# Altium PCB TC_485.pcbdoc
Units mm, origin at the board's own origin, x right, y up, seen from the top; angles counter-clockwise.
Board outline 61.6 x 60 mm, 2 copper layers (Top Layer, Bottom Layer); 41 components, 25 nets, 95 pads, 58 vias.
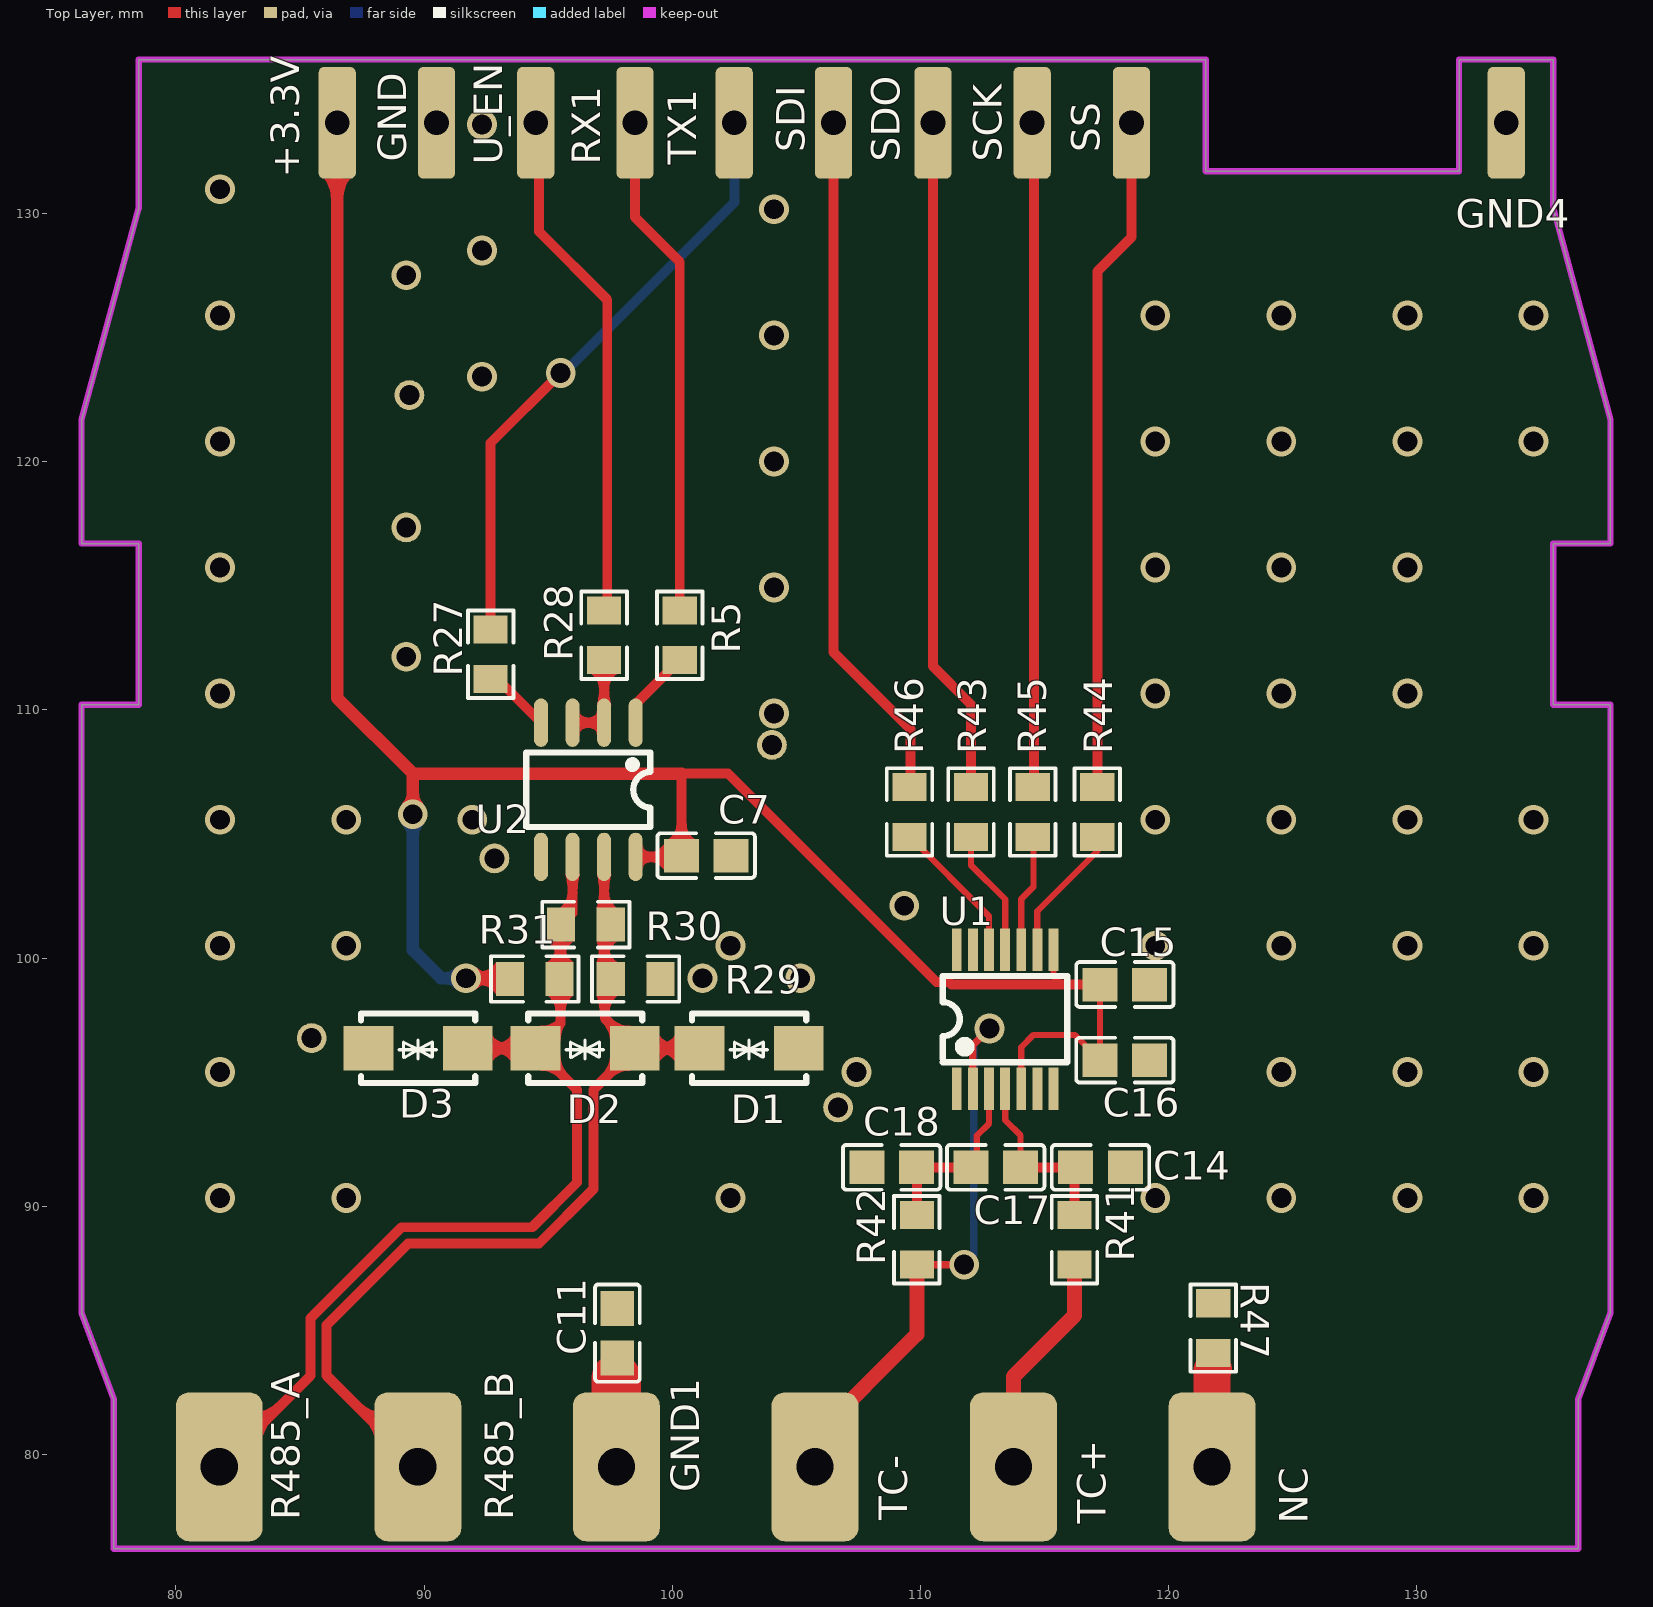
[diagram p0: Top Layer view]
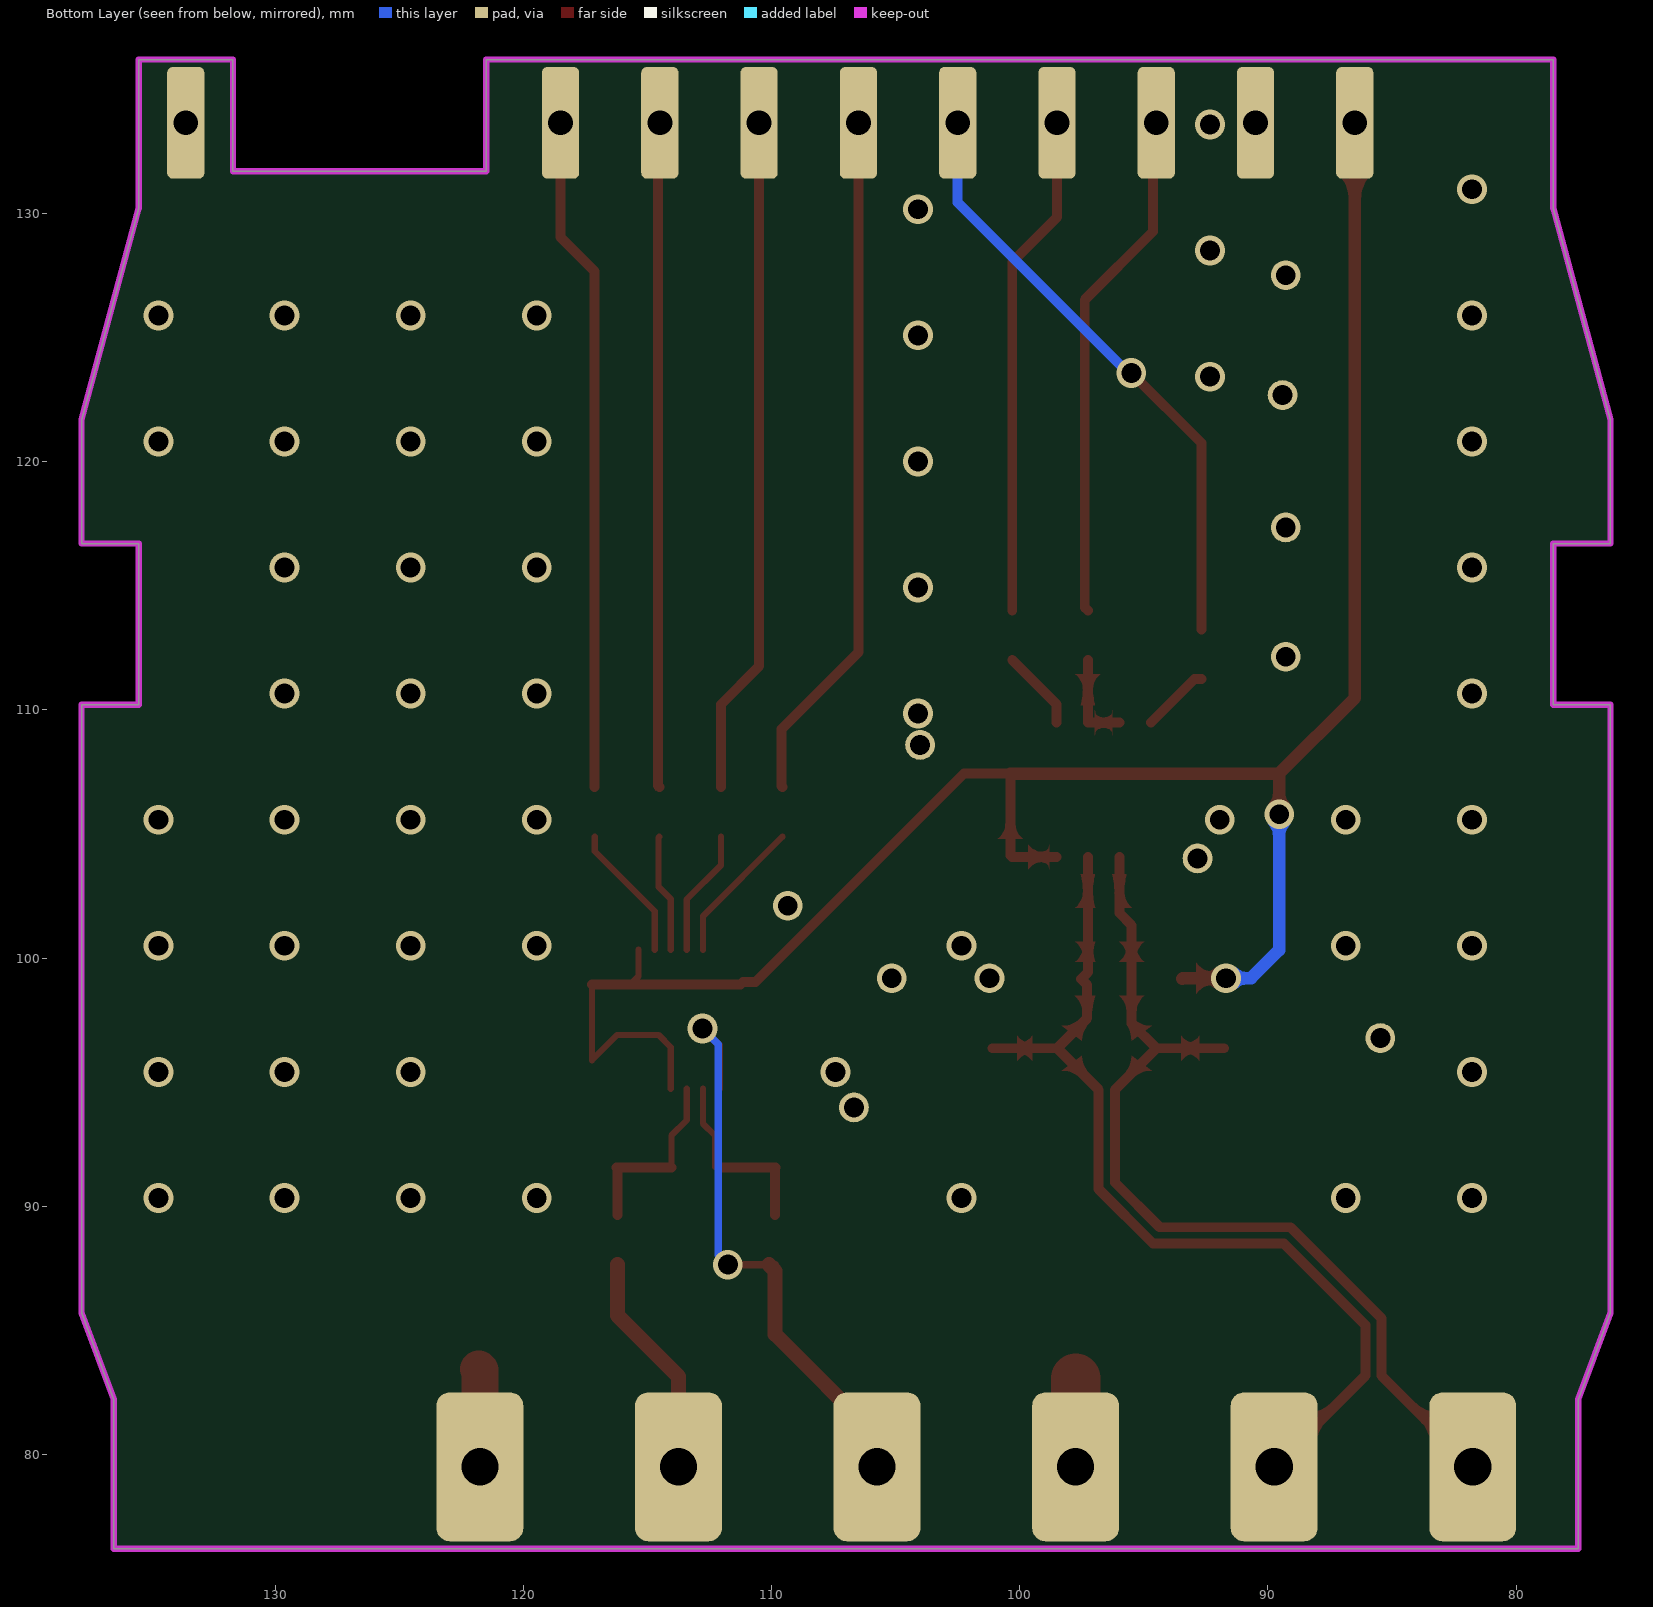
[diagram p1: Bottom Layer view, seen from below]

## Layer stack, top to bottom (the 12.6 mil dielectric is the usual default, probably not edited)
Top Layer: signal copper (thickness not stored)
Dielectric: dielectric 0.32, FR-4, Dk 4.8
Bottom Layer: signal copper (thickness not stored)

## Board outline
121.5,136.2 78.5,136.2 78.5,130.2 76.2,121.7 76.2,116.7 78.5,116.7 78.5,110.2 76.2,110.2 76.2,85.7 77.5,82.2 77.5,76.2 136.5,76.2 136.5,82.2 137.8,85.7 137.8,110.2 135.5,110.2 135.5,116.7 137.8,116.7 137.8,121.7 135.5,130.2 135.5,136.2 131.7,136.2 131.7,131.7 121.5,131.7

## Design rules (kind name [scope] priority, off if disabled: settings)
BoardOutlineClearance copperThickness1oz [All] p0: genericclearance=0.254 ignorepadtopadclearanceinfootprint=FALSE except(0: Arc-SplitContinuation Track-SplitContinuation SMDPad-SplitContinuation THPad-SplitContinuation Via-SplitContinuation Fill-SplitContinuation Poly-SplitContinuation Region-SplitContinuation Text-SplitContinuation; 0.203: SMDPad-OutlineEdge THPad-OutlineEdge Via-OutlineEdge; 0.254: Track-CutoutEdge SMDPad-CutoutEdge THPad-CutoutEdge Via-CutoutEdge Fill-CutoutEdge Region-CutoutEdge; 0.305: Track-OutlineEdge Fill-OutlineEdge Region-OutlineEdge Poly-OutlineEdge Text-OutlineEdge)
BoardOutlineClearance copperThickness2oz [All] p0: genericclearance=0.254 ignorepadtopadclearanceinfootprint=FALSE except(0: Arc-SplitContinuation Track-SplitContinuation SMDPad-SplitContinuation THPad-SplitContinuation Via-SplitContinuation Fill-SplitContinuation Poly-SplitContinuation Region-SplitContinuation Text-SplitContinuation; 0.152: Track-CutoutEdge SMDPad-CutoutEdge THPad-CutoutEdge Via-CutoutEdge Region-CutoutEdge; 0.3: Track-OutlineEdge SMDPad-OutlineEdge THPad-OutlineEdge Via-OutlineEdge Fill-OutlineEdge Region-OutlineEdge Poly-OutlineEdge Text-OutlineEdge Fill-CutoutEdge)
Clearance copperThickness1oz [(InNet('+3.3V') OR InNet('GND') OR InNet('R485_B') OR InNet('R485_A') OR InNet('$3N638') OR InNet('U1_RX') OR InNet('$3N640') OR InNet('U1_TX') OR InNet('$3N639') OR InNet('U1_EN') OR InNet('SDO') OR InNet('SS') OR InNet('SCLK') OR InNet('SDI') OR InNet('GND1') OR InNet('THERM+') OR InNet('THERM-') OR InNet('$2N3925') OR InNet('$2N8941') OR InNet('$2N8947') OR InNet('$2N8951') OR InNet('$2N8954') OR InNet('$2N8955') OR InNet('$2N8952') OR InNet('DRDY'))] p1: gap=0.178 ignorepadtopadclearanceinfootprint=FALSE except(0.203: SMDPad-Sheet THPad-Sheet Via-Sheet; 0.239: SMDPad-SMDPad; 0.254: Track-Track Track-SMDPad Track-THPad SMDPad-THPad THPad-THPad Track-Via SMDPad-Via THPad-Via Via-Via SMDPad-Fill THPad-Fill Via-Fill Fill-Fill Track-Region SMDPad-Region THPad-Region Via-Region Fill-Region Region-Region Track-Poly SMDPad-Poly THPad-Poly Via-Poly Fill-Poly Region-Poly Poly-Poly Track-Text SMDPad-Text THPad-Text Via-Text Fill-Text Region-Text Poly-Text Text-Text Track-Hole SMDPad-Hole THPad-Hole Via-Hole Fill-Hole Region-Hole Poly-Hole Text-Hole Sheet-Hole; 0.305: Track-Fill Track-Sheet Fill-Sheet Region-Sheet Poly-Sheet Text-Sheet)
Clearance copperThickness2oz [All] p1: gap=0.178 ignorepadtopadclearanceinfootprint=FALSE except(0.152: Track-SMDPad SMDPad-SMDPad Track-THPad SMDPad-THPad THPad-THPad Track-Via SMDPad-Via THPad-Via Via-Via SMDPad-Fill THPad-Fill Via-Fill Fill-Fill Track-Region SMDPad-Region THPad-Region Via-Region Region-Region Track-Poly SMDPad-Poly THPad-Poly Via-Poly Fill-Poly Region-Poly Poly-Poly Track-Text SMDPad-Text THPad-Text Via-Text Fill-Text Region-Text Poly-Text Text-Text; 0.175: Track-Hole SMDPad-Hole THPad-Hole Via-Hole Fill-Hole Region-Hole Poly-Hole Text-Hole Sheet-Hole; 0.203: Track-Track; 0.3: Track-Fill Fill-Region Track-Sheet SMDPad-Sheet THPad-Sheet Via-Sheet Fill-Sheet Region-Sheet Poly-Sheet Text-Sheet)
DiffPairsRouting differentialPair [All] p1: maxuncoupledlength=10 minlimit=10 maxlimit=10 mostfreqgap=10 toplayer_minwidth=10 toplayer_prefwidth=15.748 toplayer_maxwidth=100 bottomlayer_minwidth=10 bottomlayer_prefwidth=15.748 bottomlayer_maxwidth=100
PasteMaskExpansion pasteMaskExpansion [All] p1: expansion=0
PlaneConnect innerPlane [All] p1: planeconnectstyle=Relief reliefexpansion=0.508 reliefentries=4 reliefconductorwidth=0.254 reliefairgap=0.254
PolygonConnect copperRegion [All] p1: connectstyle=Direct reliefentries=4 reliefconductorwidth=10 polygonreliefangle="90 Angle" airgapwidth=10
RoutingVias viaSize [All] p1: viastyle="Through Hole" holewidth=31.496 minholewidth=11.811 maxholewidth=247.9922 width=47.244 minwidth=19.685 maxwidth=393.7008
SolderMaskExpansion solderMaskExpansion [All] p1: useseparateexpansions=TRUE expansion=2.0079 expansionbottom=2.0079
Width copperThickness1oz [All] p1: maxlimit=100 minlimit=5 preferedwidth=10
Width copperThickness2oz [All] p1: maxlimit=100 minlimit=8 preferedwidth=10

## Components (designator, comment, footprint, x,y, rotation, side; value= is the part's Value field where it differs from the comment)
+3.3V "S_TM" S_FT 86.5,133.65 r0 top
C7 "CC0805KRX7R9BB104" C0805 101.366,104.128 r180 top
C11 "0805B102K102CT" C0805 97.79,84.888 r90 top
C14 "CC0805KRX7R9BB103" C0805 117.253,91.567 r180 top
C15 "CC0805KRX7R9BB104" C0805 118.237,98.933 r0 top
C16 "CC0805KRX7R9BB104" C0805 118.237,95.885 r0 top
C17 "CC0805KRX7R9BB104" C0805 113.03,91.567 r180 top
C18 "CC0805KRX7R9BB103" C0805 108.839,91.567 r0 top
D1 "SMAJ12CA_C152122" SMA_L4.4-W2.6-LS5.0-BI 103.096,96.365 r0 top
D2 "SMAJ12CA_C152122" SMA_L4.4-W2.6-LS5.0-BI 96.492,96.365 r0 top
D3 "SMAJ12CA_C152122" SMA_L4.4-W2.6-LS5.0-BI 89.761,96.365 r0 top
GND "S_TM" S_FT 90.5,133.65 r0 top
GND1 "B_TM" B_FT 97.75,79.5 r180 top
GND4 "S_TM" S_FT 133.6,133.65 r180 top
NC "B_TM" B_FT 121.75,79.5 r180 top
R5 "RC0805FR-071KL" R0805 100.302,113.002 r270 top
R27 "RC0805FR-071KL" R0805 92.682,112.24 r270 top
R28 "RC0805FR-071KL" R0805 97.254,113.002 r270 top
R29 "RC0805FR-074K7L" R0805 98.524,99.159 r0 top
R30 "RC0805FR-07120RL" R0805 96.52,101.346 r0 top
R31 "RC0805FR-074K7L" R0805 94.46,99.159 r0 top
R41 "RC0805FR-07100RL" R0805 116.205,88.646 r270 top
R42 "RC0805FR-07100RL" R0805 109.855,88.646 r270 top
R43 "RC0805JR-070RL" R0805 112.035,105.883 r270 top
R44 "RC0805JR-070RL" R0805 117.125,105.883 r270 top
R45 "RC0805JR-070RL" R0805 114.521,105.883 r270 top
R46 "RC0805JR-070RL" R0805 109.562,105.883 r270 top
R47 "RC0805JR-070RL" R0805 121.793,85.09 r270 top
R485_A "B_TM" B_FT 81.75,79.5 r180 top
R485_B "B_TM" B_FT 89.75,79.5 r180 top
RX1 "S_TM" S_FT 98.5,133.65 r180 top
SCK "S_TM" S_FT 114.5,133.65 r180 top
SDI "S_TM" S_FT 106.5,133.65 r180 top
SDO "S_TM" S_FT 110.5,133.65 r180 top
SS "S_TM" S_FT 118.5,133.65 r180 top
TC+ "B_TM" B_FT 113.75,79.5 r180 top
TC- "B_TM" B_FT 105.75,79.5 r180 top
TX1 "S_TM" S_FT 102.5,133.65 r180 top
U1 "MAX31856MUD+T" TSSOP-14_L5.0-W4.4-P0.65-LS6.4-BL 113.411,97.536 r0 top
U2 "SP3485EN-L/TR" SOIC-8_L5.0-W4.0-P1.27-LS6.0-BL 96.619,106.779 r180 top
U_EN "S_TM" S_FT 94.5,133.65 r180 top

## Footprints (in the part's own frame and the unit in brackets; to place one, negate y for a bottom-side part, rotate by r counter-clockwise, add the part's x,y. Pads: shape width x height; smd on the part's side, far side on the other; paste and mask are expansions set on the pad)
B_FT [mm]
  rrect30% 3.5x6 hole 1.5: 1(0,0)
C0805 [mm]
  rect 1.41x1.35 smd: 1(-1,0) 2(1,0)
  silkscreen extent -1.96,-0.9 1.96,0.9
R0805 [mm]
  rect 1.133x1.377 smd: 1(-1,0) 2(1,0)
  silkscreen extent -1.76,-0.92 1.76,0.92
S_FT [mm]
  rrect30% 1.5x4.5 hole 1: 1(0,0)
SMA_L4.4-W2.6-LS5.0-BI [mm]
  rect 2x1.8 smd: 1(-2,0) 2(2,0)
  silkscreen extent -2.3,-1.4 2.3,1.4
SOIC-8_L5.0-W4.0-P1.27-LS6.0-BL [mil]
  oval 22.38x76.78 smd: 1(-75,-106.5) 2(-25,-106.5) 3(25,-106.5) 4(75,-106.5) 5(75,106.5) 6(25,106.5) 7(-25,106.5) 8(-75,106.5)
  silkscreen extent -98,-59 98,59
TSSOP-14_L5.0-W4.4-P0.65-LS6.4-BL [mm]
  rect 0.4x1.7 smd: 1(-1.95,-2.8) 2(-1.3,-2.8) 3(-0.65,-2.8) 4(0,-2.8) 5(0.65,-2.8) 6(1.3,-2.8) 7(1.95,-2.8) 8(1.95,2.8) 9(1.3,2.8) 10(0.65,2.8) 11(0,2.8) 12(-0.65,2.8) 13(-1.3,2.8) 14(-1.95,2.8)
  silkscreen extent -2.51,-1.74 2.5,1.74

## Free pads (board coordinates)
  round 1.2 hole 0.8: 1(85.471,96.774) 1(89.281,112.141) 1(89.281,117.348) 1(89.281,127.508) 1(89.408,122.682) 1(92.837,104.013) 1(101.219,99.187) 1(104.013,108.585) 1(105.156,99.187) 1(106.68,93.98) 1(109.347,102.108)

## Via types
v1: diameter 1.2, hole 0.8, Top Layer to Bottom Layer, 58 vias

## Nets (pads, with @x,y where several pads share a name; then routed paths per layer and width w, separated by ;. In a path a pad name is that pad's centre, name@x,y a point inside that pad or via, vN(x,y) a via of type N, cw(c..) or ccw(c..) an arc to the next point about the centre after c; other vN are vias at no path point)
$2N3925: NC.1 R47.2 | length 4
  Top Layer w1.5: NC.1 121.75,83.396 121.793,83.439
$2N8941: C14.2 C17.1 R41.1 U1.4 | length 7.6
  Top Layer w0.254: U1.4 113.411,93.472 114.03,92.853 C17.1
  Top Layer w0.4: C17.1 C14.2 116.205,91.519 R41.1
$2N8947: C17.2 C18.2 R42.1 U1.3 | length 7.5
  Top Layer w0.254: C17.2@112.014,91.583 C17.2 ; C17.2@112.268,91.583 112.268,92.837 112.761,93.33 U1.3
  Top Layer w0.4: R42.1 109.855,91.551 C18.2 C17.2
$2N8951: R43.2 U1.11 | length 5.1
  Top Layer w0.254: R43.2 112.035,103.738 113.411,102.362 U1.11
$2N8952: R46.2 U1.12 | length 5.9
  Top Layer w0.254: R46.2 112.761,101.684 U1.12
$2N8954: R44.2 U1.9 | length 5.5
  Top Layer w0.254: U1.9 114.711,101.884 117.125,104.298 R44.2
$2N8955: R45.2 U1.10 | length 4.8
  Top Layer w0.254: U1.10 114.061,102.377 114.554,102.87 114.554,104.851 R45.2
$3N638: R5.2 U2.1 | length 3.3
  Top Layer w0.4: U2.1 98.524,110.224 R5.2
$3N639: R28.2 U2.2 U2.3 | length 3.8
  Top Layer w0.4: U2.3 U2.2 R28.2
$3N640: R27.2 U2.4 | length 2.8
  Top Layer w0.4: R27.2 92.958,111.24 U2.4
+3.3V: +3.3V.1 C7.2 C15.1 C16.1 R31.1 U1.5 U1.8 U2.8 | length 85.4
  Top Layer w0.254: U1.5 114.061,96.408 114.554,96.901 116.221,96.901 C16.1 C15.1 ; U1.8 115.361,99.269 115.697,98.933
  Top Layer w0.4: U2.8 100.312,104.074 C7.2 100.377,104.139 100.377,107.43 102.247,107.43 110.645,99.032 111.153,99.032 111.252,98.933 115.697,98.933 C15.1
  Top Layer w0.5: +3.3V.1 86.5,110.477 89.547,107.43 ; v1(89.547,105.791) 89.547,107.43 ; v1(91.694,99.187) 93.432,99.187 R31.1 ; 100.377,107.43 89.547,107.43
  Bottom Layer w0.5: v1(89.547,105.791) 89.547,100.318 90.678,99.187 v1(91.694,99.187)
DRDY: U1.7
GND: C7.1 C11.2 C14.1 C15.2 C16.2 C18.1 D1.2 D3.1 GND4.1 GND.1 pad.1 R29.2 R47.1 U1.1 U1.14 U2.5
  other v1: 81.784,90.333 86.864,90.333 102.348,90.333 119.46,90.333 124.54,90.333 129.62,90.333 134.7,90.333 81.784,95.413 107.428,95.413 124.54,95.413 129.62,95.413 134.7,95.413 81.784,100.493 86.864,100.493 102.348,100.493 119.46,100.493 124.54,100.493 129.62,100.493 134.7,100.493 81.784,105.573 86.864,105.573 91.944,105.573 119.46,105.573 124.54,105.573 129.62,105.573 134.7,105.573 104.104,109.849 81.784,110.653 119.46,110.653 124.54,110.653 129.62,110.653 104.104,114.929 81.784,115.733 119.46,115.733 124.54,115.733 129.62,115.733 104.104,120.009 81.784,120.813 119.46,120.813 124.54,120.813 129.62,120.813 134.7,120.813 92.334,123.424 104.104,125.089 81.784,125.893 119.46,125.893 124.54,125.893 129.62,125.893 134.7,125.893 92.334,128.504 104.104,130.169 81.784,130.973 92.334,133.584
GND1: C11.1 GND1.1 | length 3.6
  Top Layer w2: GND1.1 97.75,83.058
R485_A: D2.1 D3.2 R30.1 R31.2 R485_A.1 U2.6 | length 37.7
  Top Layer w0.4: R485_A.1 85.423,83.173 85.423,85.488 89.089,89.154 94.361,89.154 96.165,90.958 96.165,94.692 D2.1 ; D3.2 D2.1 ; U2.6 95.984,101.81 95.492,101.318 95.492,97.365 D2.1
R485_B: D1.1 D2.2 R29.1 R30.2 R485_B.1 U2.7 | length 37.6
  Top Layer w0.4: R485_B.1 86.077,83.173 86.077,85.217 89.36,88.5 94.632,88.5 96.819,90.687 96.819,94.692 D2.2 ; U2.7 97.254,99.429 R29.1 97.282,98.917 97.282,97.575 D2.2 ; D1.1 D2.2
SCLK: R45.1 SCK.1 | length 26.8
  Top Layer w0.4: SCK.1 114.581,133.569 114.581,106.942 R45.1
SDI: R46.1 SDI.1 | length 28.1
  Top Layer w0.4: SDI.1 106.5,112.321 109.601,109.22 109.601,106.923 R46.1
SDO: R43.1 SDO.1 | length 27.4
  Top Layer w0.4: SDO.1 110.5,111.755 112.035,110.22 R43.1
SS: R44.1 SS.1 | length 27.3
  Top Layer w0.4: R44.1 117.125,127.666 118.5,129.041 SS.1
THERM+: R41.2 TC+.1 | length 9.2
  Top Layer w0.6: TC+.1 113.75,83.143 116.205,85.598 R41.2
THERM-: R42.2 TC-.1 U1.2 | length 24.5
  Top Layer w0.3: R42.2 110.109,87.646 v1(111.76,87.646) ; U1.2 112.111,96.49 v1(112.776,97.155)
  Top Layer w0.6: TC-.1 105.75,80.731 109.855,84.836 109.855,87.392 R42.2@110.109,87.646
  Bottom Layer w0.3: v1(111.76,87.646) 112.141,88.027 112.141,96.52 v1(112.776,97.155)
U1_EN: R28.1 U_EN.1 | length 20.9
  Top Layer w0.4: U_EN.1 94.627,133.523 94.627,129.274 97.381,126.52 97.381,114.129 R28.1
U1_RX: R5.1 RX1.1 | length 20.4
  Top Layer w0.4: RX1.1 98.5,129.846 100.302,128.044 R5.1
U1_TX: R27.1 TX1.1 | length 24.6
  Top Layer w0.4: R27.1 92.682,120.749 v1(95.504,123.571)
  Bottom Layer w0.4: v1(95.504,123.571) 95.631,123.571 102.5,130.44 TX1.1
pads on no net: U1.6 U1.13

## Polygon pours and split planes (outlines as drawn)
GND on Top Layer (solid, remove dead copper, pour order 0): 76.2,116.7 78.5,116.7 78.5,110.2 76.2,110.2 76.2,85.151 137.8,85.151 137.8,110.2 135.5,110.2 135.5,116.7 137.8,116.7 137.8,121.7 135.5,130.2 135.5,136.2 131.7,136.2 131.7,131.7 121.5,131.7 121.5,136.2 78.5,136.2 78.5,130.2 76.2,121.7
GND on Bottom Layer (solid, remove dead copper, pour order 2): 76.2,116.7 78.5,116.7 78.5,110.2 76.2,110.2 76.2,85.151 137.8,85.151 137.8,110.2 135.5,110.2 135.5,116.7 137.8,116.7 137.8,121.7 135.5,130.2 135.5,136.2 131.7,136.2 131.7,131.7 121.5,131.7 121.5,136.2 78.5,136.2 78.5,130.2 76.2,121.7

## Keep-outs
Board Outline Layer:
  the board outline again, w0.254

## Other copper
Top Layer:
  region net +3.3V: 86.75,130.65 86.25,130.65 ccw(c85.09,130.65) 85.975,131.4 87.025,131.4 ccw(c87.91,130.65)
  region net +3.3V: 100.177,105.403 100.577,105.403 ccw(c101.327,105.403) 100.877,104.803 99.877,104.803 ccw(c99.427,105.403)
  region net +3.3V: 99.061,103.874 99.061,104.274 ccw(c99.061,105.024) 99.661,104.574 99.661,103.574 ccw(c99.061,103.124)
  region net R485_B: 99.496,96.165 99.496,96.565 ccw(c99.496,97.315) 100.096,96.865 100.096,95.865 ccw(c99.496,95.415)
  region net R485_A: 95.321,97.477 95.633,97.223 ccw(c96.694,96.658) 95.492,96.658 94.685,97.265 ccw(c94.685,98.325)
  region net R485_A: 95.704,95.436 95.321,95.253 ccw(c94.685,94.404) 94.685,95.465 95.492,96.072 ccw(c96.552,96.072)
  region net R485_A: 92.892,96.165 92.892,96.565 ccw(c92.892,97.315) 93.492,96.865 93.492,95.865 ccw(c92.892,95.415)
  region net R485_B: 97.28,97.294 97.663,97.477 ccw(c98.299,98.325) 98.299,97.265 97.492,96.658 ccw(c96.431,96.658)
  region net R485_B: 97.663,95.253 97.28,95.436 ccw(c96.431,96.072) 97.492,96.072 98.299,95.465 ccw(c98.299,94.404)
  region net R485_B: 100.092,96.565 100.092,96.165 ccw(c100.092,95.415) 99.492,95.865 99.492,96.865 ccw(c100.092,97.315)
  region net R485_A: 93.361,96.565 93.361,96.165 ccw(c93.361,95.415) 92.761,95.865 92.761,96.865 ccw(c93.361,97.315)
  region net $3N639: 97.454,110.836 97.054,110.836 ccw(c96.304,110.836) 96.754,111.436 97.754,111.436 ccw(c98.204,110.836)
  region net R485_B: 97.482,97.87 97.082,97.87 ccw(c95.573,97.87) 96.958,98.47 97.782,98.47 ccw(c98.232,97.87)
  region net R485_B: 97.054,100.447 97.454,100.447 ccw(c98.204,100.447) 97.754,99.847 96.958,99.847 ccw(c95.136,100.447)
  region net R485_B: 97.054,102.635 97.454,102.635 ccw(c98.204,102.635) 97.754,102.035 96.954,102.035 ccw(c95.206,102.635)
  region net R485_B: 97.454,100.057 97.054,100.057 ccw(c95.206,100.057) 96.954,100.657 97.754,100.657 ccw(c98.204,100.057)
  region net R485_A: 95.692,100.057 95.292,100.057 ccw(c94.542,100.057) 94.992,100.657 95.992,100.657 ccw(c96.442,100.057)
  region net R485_A: 95.784,102.635 96.184,102.635 ccw(c97.98,102.035) 96.086,102.035 95.484,102.035 ccw(c95.034,102.635)
  region net R485_A: 95.692,97.87 95.292,97.87 ccw(c94.542,97.87) 94.992,98.47 95.992,98.47 ccw(c96.442,97.87)
  region net R485_A: 95.292,100.447 95.692,100.447 ccw(c96.442,100.447) 95.992,99.847 94.992,99.847 ccw(c94.542,100.447)
  region net +3.3V: 92.144,98.937 92.144,99.437 ccw(c92.144,100.374) 92.894,99.812 92.894,98.562 ccw(c92.144,98)
  region net R485_A: 84.033,82.066 83.816,81.283 ccw(c84.699,80.4) 83.5,80.75 83.5,81.75 ccw(c83.15,82.949)
  region net R485_B: 87.684,81.283 87.467,82.066 ccw(c88.35,82.949) 88,81.75 88,80.75 ccw(c86.801,80.4)
  region net $3N639: 96.37,109.284 96.37,109.684 96.482,109.685 96.59,109.689 96.691,109.7 96.738,109.709 96.782,109.721 96.822,109.737 96.859,109.757 96.891,109.781 96.918,109.81 96.94,109.845 96.956,109.885 96.966,109.931 96.97,109.984 96.97,108.984 96.966,109.037 96.956,109.083 96.94,109.123 96.918,109.157 96.891,109.186 96.859,109.211 96.822,109.231 96.782,109.246 96.738,109.259 96.691,109.268 96.59,109.279 96.482,109.283
  region net $3N639: 97.054,110.775 97.454,110.775 97.457,110.664 97.467,110.558 97.48,110.46 97.496,110.372 97.525,110.237 97.538,110.175 96.97,110.175 96.983,110.237 97.012,110.372 97.027,110.46 97.041,110.558 97.05,110.664
  region net $3N639: 96.868,109.684 96.868,109.284 96.756,109.283 96.648,109.279 96.546,109.268 96.499,109.259 96.456,109.246 96.415,109.231 96.379,109.211 96.347,109.186 96.32,109.157 96.298,109.123 96.282,109.083 96.271,109.037 96.268,108.984 96.268,109.984 96.271,109.931 96.282,109.885 96.298,109.845 96.32,109.81 96.347,109.781 96.379,109.757 96.415,109.737 96.456,109.721 96.499,109.709 96.546,109.7 96.648,109.689 96.756,109.685
  region net +3.3V: 99.408,104.274 99.408,103.874 99.296,103.873 99.188,103.869 99.086,103.858 99.039,103.849 98.996,103.836 98.955,103.82 98.919,103.8 98.887,103.776 98.86,103.747 98.838,103.713 98.822,103.673 98.811,103.627 98.808,103.574 98.808,104.574 98.811,104.521 98.822,104.475 98.838,104.435 98.86,104.4 98.887,104.371 98.919,104.347 98.955,104.327 98.996,104.311 99.039,104.299 99.086,104.29 99.188,104.278 99.296,104.274
  region net R485_B: 97.454,102.783 97.054,102.783 97.05,102.894 97.041,103 97.027,103.098 97.012,103.186 96.983,103.321 96.97,103.383 97.538,103.383 97.525,103.321 97.496,103.186 97.48,103.098 97.467,103 97.457,102.894
  region net R485_A: 96.184,102.783 95.784,102.783 95.78,102.894 95.771,103 95.757,103.098 95.742,103.186 95.713,103.321 95.7,103.383 96.268,103.383 96.255,103.321 96.226,103.186 96.21,103.098 96.197,103 96.187,102.894
  region net +3.3V: 89.297,106.608 89.797,106.608 89.802,106.551 89.814,106.494 89.834,106.438 89.86,106.384 89.89,106.331 89.924,106.28 89.997,106.188 89.097,106.188 89.171,106.28 89.204,106.331 89.235,106.384 89.26,106.438 89.28,106.494 89.293,106.551
  region net +3.3V: 92.511,99.437 92.511,98.937 92.454,98.933 92.397,98.92 92.341,98.9 92.287,98.875 92.234,98.844 92.183,98.81 92.091,98.737 92.091,99.637 92.183,99.564 92.234,99.53 92.287,99.499 92.341,99.474 92.397,99.454 92.454,99.441
Bottom Layer:
  region net +3.3V: 89.797,104.974 89.297,104.974 89.293,105.031 89.28,105.088 89.26,105.144 89.235,105.198 89.204,105.251 89.171,105.302 89.097,105.394 89.997,105.394 89.924,105.302 89.89,105.251 89.86,105.198 89.834,105.144 89.814,105.088 89.802,105.031
  region net +3.3V: 90.877,98.937 90.877,99.437 90.934,99.441 90.991,99.454 91.047,99.474 91.101,99.499 91.154,99.53 91.205,99.564 91.297,99.637 91.297,98.737 91.205,98.81 91.154,98.844 91.101,98.875 91.047,98.9 90.991,98.92 90.934,98.933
